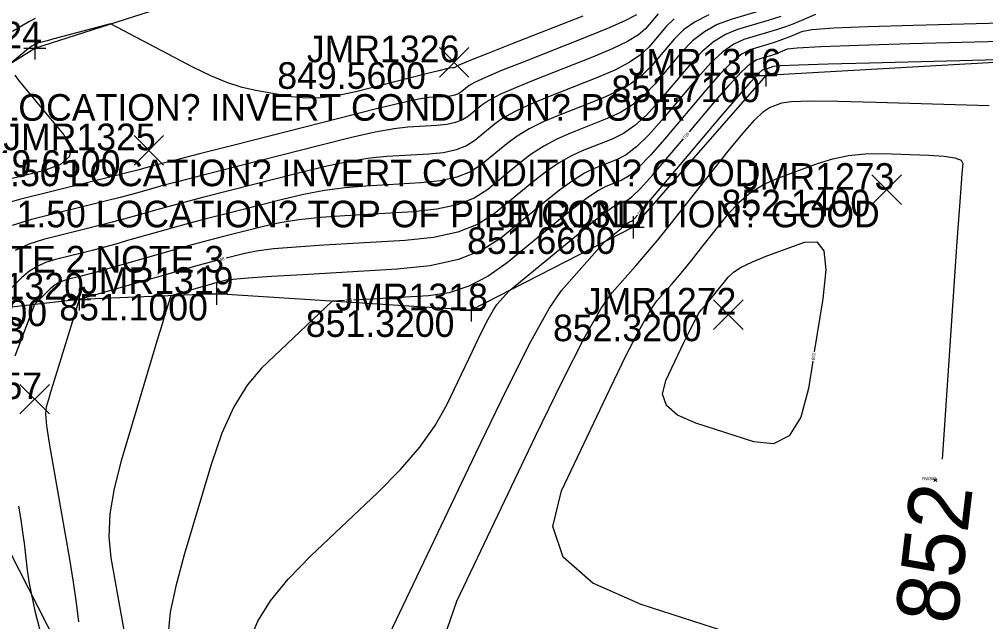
# Model space of a CAD drawing. Extents: x 1654928 to 1810050, y 486881 to 626330.
# Drawn here: x 1801470.61 to 1801514.13, y 489797.37 to 489824.51 of the extents above; entities that cross this region are included whole.
import ezdxf

# ---------------------------------------------------------------- set-up
doc = ezdxf.new("R2010")
doc.units = 0
for name, color, linetype in [('DT_X_Contour_Major', 7, 'Continuous'), ('DT_X_Contour_Minor', 7, 'Continuous'), ('GK_Visualization', 7, 'Continuous'), ('RD_X_Fence', 7, 'Continuous'), ('SV_X_Break_Lines', 7, 'Continuous'), ('SV_X_Random_Point', 7, 'Continuous'), ('SV_X_Shot_Marker', 7, 'Continuous'), ('SV_X_Text_Comment', 7, 'Continuous'), ('SV_X_Text_Elevation', 7, 'Continuous'), ('SV_X_Text_Name', 7, 'Continuous'), ('SV_X_Top_of_Bank', 7, 'Continuous')]:
    doc.layers.add(name, color=color, linetype=linetype)

msp = doc.modelspace()

# ---------------------------------------------------------------- linework, layer by layer
at = {"layer": 'DT_X_Contour_Major'}
for points in [[(1801499.38, 489824.763), (1801498.806, 489824.082), (1801498.496, 489823.811), (1801497.996, 489823.508), (1801497.307, 489823.172), (1801496.427, 489822.805), (1801493.829, 489821.783), (1801492.948, 489821.425), (1801492.255, 489821.116), (1801491.749, 489820.857), (1801491.431, 489820.646), (1801490.831, 489820.152), (1801490.574, 489819.987), (1801490.25, 489819.86), (1801489.862, 489819.773), (1801489.407, 489819.725), (1801488.108, 489819.65), (1801487.495, 489819.578), (1801486.631, 489819.417), (1801485.515, 489819.168), (1801484.147, 489818.83), (1801478.825, 489817.469), (1801477.797, 489817.203), (1801477.078, 489817.014), (1801476.67, 489816.903), (1801475.994, 489816.709), (1801475.656, 489816.616), (1801475.15, 489816.484), (1801474.475, 489816.312), (1801471.158, 489815.484), (1801470.29, 489815.226)], [(1801506.463, 489824.72), (1801505.733, 489824.408), (1801505.441, 489824.29), (1801505.113, 489824.17), (1801504.749, 489824.049), (1801504.348, 489823.925), (1801503.231, 489823.594), (1801502.788, 489823.394), (1801502.296, 489823.043), (1801501.755, 489822.542), (1801501.166, 489821.889), (1801499.53, 489819.947), (1801498.945, 489819.291), (1801498.416, 489818.778), (1801497.944, 489818.41), (1801497.528, 489818.186), (1801496.495, 489817.78), (1801496.064, 489817.57), (1801495.546, 489817.248), (1801494.941, 489816.812), (1801494.249, 489816.262), (1801492.287, 489814.645), (1801491.445, 489814.102), (1801490.387, 489813.689), (1801489.115, 489813.404), (1801487.628, 489813.248), (1801483.376, 489813.002), (1801481.964, 489812.917), (1801480.917, 489812.847), (1801480.234, 489812.79), (1801479.916, 489812.749), (1801479.554, 489812.656), (1801479.4, 489812.616), (1801479.211, 489812.564), (1801478.987, 489812.501), (1801477.431, 489812.055), (1801477.137, 489811.108), (1801477.034, 489810.768), (1801476.848, 489810.152), (1801475.196, 489804.621), (1801474.875, 489803.37), (1801474.691, 489802.225), (1801474.644, 489801.185), (1801474.734, 489800.25), (1801475.156, 489797.899), (1801475.311, 489796.983)], [(1801497.199, 489807.839), (1801497.945, 489809.374), (1801498.547, 489810.55), (1801499.007, 489811.366), (1801499.323, 489811.822), (1801499.974, 489812.559), (1801500.244, 489812.872), (1801500.563, 489813.255), (1801500.933, 489813.71), (1801501.352, 489814.236), (1801502.537, 489815.733), (1801503.01, 489816.256), (1801503.539, 489816.699), (1801504.125, 489817.064), (1801504.767, 489817.351), (1801506.556, 489818.01), (1801507.241, 489818.223), (1801507.956, 489818.369), (1801508.699, 489818.446), (1801509.471, 489818.456), (1801511.568, 489818.391), (1801512.253, 489818.349), (1801512.738, 489818.271), (1801513.022, 489818.158), (1801513.104, 489818.009), (1801513.056, 489817.564), (1801513.02, 489817.111), (1801512.947, 489816.088), (1801512.836, 489814.493), (1801512.247, 489805.791), (1801512.167, 489804.693)], [(1801511.18, 489796.356), (1801511.157, 489796.211), (1801510.687, 489795.44), (1801509.604, 489795.13), (1801507.907, 489795.282), (1801505.597, 489795.895), (1801498.619, 489798.146), (1801496.431, 489799.099), (1801495.102, 489800.27), (1801494.631, 489801.658), (1801495.019, 489803.265), (1801497.199, 489807.839)]]:
    msp.add_lwpolyline(points, dxfattribs=at)
at = {"layer": 'DT_X_Contour_Minor'}
for points in [[(1801501.666, 489824.705), (1801501.043, 489824.395), (1801500.519, 489824.031), (1801500.094, 489823.614), (1801499.096, 489822.428), (1801498.676, 489822.003), (1801498.164, 489821.616), (1801497.562, 489821.267), (1801496.868, 489820.957), (1801494.895, 489820.182), (1801494.195, 489819.883), (1801493.571, 489819.569), (1801493.026, 489819.239), (1801492.558, 489818.893), (1801491.414, 489817.949), (1801490.922, 489817.633), (1801490.305, 489817.392), (1801489.563, 489817.225), (1801488.695, 489817.134), (1801486.215, 489816.991), (1801485.283, 489816.914), (1801484.345, 489816.789), (1801483.402, 489816.617), (1801482.454, 489816.398), (1801479.92, 489815.75), (1801479.02, 489815.517), (1801478.223, 489815.307), (1801477.527, 489815.118), (1801476.933, 489814.952), (1801475.484, 489814.536), (1801474.951, 489814.385), (1801474.437, 489814.244), (1801473.944, 489814.114), (1801473.47, 489813.993), (1801472.233, 489813.685), (1801471.789, 489813.546), (1801471.385, 489813.36), (1801471.02, 489813.127), (1801470.696, 489812.847), (1801469.273, 489811.433)], [(1801498.406, 489824.715), (1801497.912, 489824.454), (1801497.179, 489824.125), (1801496.207, 489823.729), (1801493.296, 489822.584), (1801492.325, 489822.196), (1801491.597, 489821.89), (1801491.111, 489821.666), (1801490.867, 489821.523), (1801490.54, 489821.254), (1801490.399, 489821.163), (1801490.223, 489821.095), (1801490.011, 489821.047), (1801489.763, 489821.021), (1801489.055, 489820.98), (1801488.602, 489820.91), (1801487.774, 489820.731), (1801486.571, 489820.444), (1801484.993, 489820.047), (1801480.286, 489818.843), (1801478.728, 489818.444), (1801477.584, 489818.15), (1801476.854, 489817.962), (1801476.538, 489817.878), (1801476.249, 489817.795), (1801476.009, 489817.731), (1801475.506, 489817.604), (1801474.74, 489817.411), (1801473.712, 489817.155), (1801470.62, 489816.384), (1801469.571, 489816.097)], [(1801495.987, 489824.653), (1801492.762, 489823.385), (1801491.702, 489822.967), (1801490.938, 489822.663), (1801490.472, 489822.474), (1801490.303, 489822.4), (1801490.249, 489822.355), (1801490.225, 489822.34), (1801490.196, 489822.329), (1801490.161, 489822.321), (1801490.119, 489822.317), (1801490.001, 489822.31), (1801489.853, 489822.28), (1801489.497, 489822.194), (1801488.934, 489822.053), (1801488.162, 489821.857), (1801485.829, 489821.26), (1801484.988, 489821.078), (1801484.215, 489820.977), (1801483.51, 489820.958), (1801482.873, 489821.021), (1801481.265, 489821.299), (1801480.637, 489821.443), (1801479.959, 489821.665), (1801479.231, 489821.966), (1801478.454, 489822.345), (1801474.71, 489824.3), (1801472.573, 489823.732), (1801472.166, 489823.624), (1801471.862, 489823.543), (1801471.562, 489823.463), (1801471.436, 489823.429), (1801471.39, 489823.415), (1801471.347, 489823.399), (1801471.307, 489823.38), (1801471.27, 489823.36), (1801471.174, 489823.303), (1801471.126, 489823.27), (1801471.052, 489823.215), (1801470.953, 489823.136), (1801470.829, 489823.035), (1801470.191, 489822.507)], [(1801504.416, 489825.023), (1801502.67, 489824.505), (1801502.04, 489824.268), (1801501.46, 489823.944), (1801500.931, 489823.535), (1801500.452, 489823.039), (1801499.241, 489821.601), (1801498.765, 489821.099), (1801498.248, 489820.67), (1801497.689, 489820.315), (1801497.088, 489820.034), (1801495.429, 489819.381), (1801494.818, 489819.112), (1801494.23, 489818.795), (1801493.664, 489818.43), (1801493.122, 489818.016), (1801491.705, 489816.848), (1801491.096, 489816.456), (1801490.332, 489816.157), (1801489.413, 489815.952), (1801488.34, 489815.839), (1801485.269, 489815.661), (1801484.177, 489815.582), (1801483.202, 489815.475), (1801482.346, 489815.341), (1801481.608, 489815.181), (1801479.798, 489814.718), (1801479.118, 489814.542), (1801478.436, 489814.359), (1801477.751, 489814.171), (1801477.064, 489813.976), (1801475.229, 489813.45), (1801474.598, 489813.27), (1801474.081, 489813.124), (1801473.678, 489813.014), (1801473.389, 489812.939), (1801472.771, 489812.785), (1801472.549, 489812.715), (1801472.347, 489812.622), (1801472.164, 489812.506), (1801472.002, 489812.366), (1801471.291, 489811.659), (1801470.402, 489809.332)], [(1801504.896, 489824.632), (1801504.382, 489824.474), (1801502.95, 489824.05), (1801502.414, 489823.831), (1801501.878, 489823.494), (1801501.343, 489823.038), (1801500.809, 489822.464), (1801499.385, 489820.774), (1801498.855, 489820.195), (1801498.332, 489819.724), (1801497.816, 489819.363), (1801497.308, 489819.11), (1801495.962, 489818.58), (1801495.441, 489818.341), (1801494.888, 489818.021), (1801494.303, 489817.621), (1801493.685, 489817.139), (1801491.996, 489815.746), (1801491.27, 489815.279), (1801490.36, 489814.923), (1801489.264, 489814.678), (1801487.984, 489814.543), (1801484.323, 489814.332), (1801483.07, 489814.249), (1801482.06, 489814.161), (1801481.29, 489814.066), (1801480.762, 489813.965), (1801479.922, 489813.75)], [(1801471.323, 489824.552), (1801471.038, 489824.396), (1801470.306, 489823.96)], [(1801500.106, 489824.528), (1801499.737, 489824.188), (1801498.951, 489823.255), (1801498.586, 489822.907), (1801498.08, 489822.562), (1801497.434, 489822.22), (1801496.647, 489821.881), (1801494.362, 489820.983), (1801493.571, 489820.654), (1801492.913, 489820.342), (1801492.387, 489820.048), (1801491.994, 489819.77), (1801491.122, 489819.051), (1801490.748, 489818.81), (1801490.278, 489818.626), (1801489.712, 489818.499), (1801489.051, 489818.43), (1801487.162, 489818.321), (1801486.389, 489818.246), (1801485.488, 489818.103), (1801484.458, 489817.893), (1801483.301, 489817.614), (1801480.042, 489816.781), (1801478.923, 489816.493), (1801478.01, 489816.255), (1801477.303, 489816.066), (1801476.801, 489815.927), (1801475.739, 489815.622), (1801475.303, 489815.5), (1801474.794, 489815.364), (1801474.209, 489815.213), (1801473.551, 489815.047), (1801471.695, 489814.584), (1801471.029, 489814.376), (1801470.423, 489814.097)], [(1801517.098, 489824.395), (1801510.885, 489824.235), (1801508.823, 489824.172), (1801507.293, 489824.103), (1801506.296, 489824.028), (1801505.833, 489823.947), (1801505.309, 489823.723), (1801505.099, 489823.638), (1801504.864, 489823.552), (1801504.602, 489823.465), (1801504.314, 489823.376), (1801503.512, 489823.138), (1801503.162, 489822.957), (1801502.714, 489822.593), (1801502.168, 489822.045), (1801501.524, 489821.314), (1801499.675, 489819.12), (1801499.035, 489818.387), (1801498.5, 489817.833), (1801498.071, 489817.458), (1801497.748, 489817.262), (1801497.028, 489816.979), (1801496.687, 489816.799), (1801496.205, 489816.474), (1801495.58, 489816.003), (1801494.813, 489815.385), (1801492.579, 489813.543), (1801491.729, 489812.932), (1801490.857, 489812.48), (1801489.962, 489812.188), (1801489.043, 489812.054), (1801485.679, 489811.86)], [(1801500.788, 489819.442), (1801501.881, 489820.739), (1801502.58, 489821.549), (1801503.132, 489822.142), (1801503.536, 489822.52), (1801503.792, 489822.683), (1801504.28, 489822.827), (1801504.455, 489822.881), (1801504.614, 489822.934), (1801504.757, 489822.986), (1801504.885, 489823.038), (1801505.203, 489823.174), (1801505.638, 489823.228), (1801506.702, 489823.285), (1801508.395, 489823.347), (1801510.719, 489823.412), (1801517.754, 489823.593)], [(1801498.72, 489816.002), (1801499.214, 489816.579), (1801499.965, 489817.466), (1801502.238, 489820.164), (1801502.992, 489821.052), (1801503.549, 489821.692), (1801503.91, 489822.083), (1801504.073, 489822.227), (1801504.246, 489822.278), (1801504.308, 489822.297), (1801504.365, 489822.316), (1801504.415, 489822.335), (1801504.461, 489822.353), (1801504.574, 489822.401), (1801504.875, 489822.424), (1801505.695, 489822.456), (1801507.033, 489822.497), (1801508.89, 489822.546), (1801518.763, 489822.8)], [(1801470.411, 489821.994), (1801470.608, 489821.729), (1801470.918, 489821.341), (1801471.341, 489820.829), (1801472.617, 489819.301), (1801472.918, 489818.77), (1801472.865, 489818.323), (1801472.456, 489817.962), (1801471.692, 489817.685), (1801469.182, 489817.059)], [(1801489.437, 489795.771), (1801490.318, 489798.3), (1801493.86, 489805.733), (1801495.072, 489808.228), (1801496.051, 489810.138), (1801496.797, 489811.465), (1801497.311, 489812.206), (1801498.37, 489813.405), (1801498.808, 489813.912), (1801499.327, 489814.535), (1801499.927, 489815.274), (1801500.609, 489816.129), (1801502.534, 489818.562), (1801503.192, 489819.37), (1801503.722, 489819.969), (1801504.123, 489820.36), (1801504.395, 489820.541), (1801504.95, 489820.745), (1801505.371, 489820.805), (1801506.217, 489820.831), (1801507.489, 489820.823), (1801509.186, 489820.781), (1801514.279, 489820.623)], [(1801480.992, 489796.533), (1801481.349, 489797.394), (1801481.926, 489798.313), (1801482.722, 489799.292), (1801483.738, 489800.33), (1801486.737, 489803.175), (1801487.776, 489804.223), (1801488.642, 489805.232), (1801489.335, 489806.201), (1801489.856, 489807.132), (1801491.014, 489809.562), (1801491.409, 489810.376), (1801491.724, 489810.996), (1801491.961, 489811.421), (1801492.119, 489811.653), (1801492.673, 489812.279), (1801495.881, 489814.924), (1801496.502, 489815.428), (1801496.989, 489815.804), (1801497.342, 489816.055), (1801497.562, 489816.178), (1801497.969, 489816.338), (1801498.199, 489816.505), (1801498.584, 489816.887), (1801499.124, 489817.483), (1801499.82, 489818.293), (1801500.517, 489819.121)], [(1801487.107, 489796.463), (1801491.16, 489804.967), (1801492.542, 489807.817), (1801493.647, 489809.986), (1801494.476, 489811.476), (1801495.03, 489812.285), (1801496.967, 489814.477), (1801497.707, 489815.088), (1801497.85, 489815.204), (1801497.963, 489815.291), (1801498.044, 489815.349), (1801498.095, 489815.377), (1801498.189, 489815.414), (1801498.326, 489815.553), (1801498.444, 489815.686)], [(1801500.538, 489809.944), (1801500.818, 489810.52), (1801501.044, 489810.961), (1801501.216, 489811.267), (1801501.334, 489811.438), (1801501.579, 489811.714), (1801501.68, 489811.832), (1801501.799, 489811.975), (1801501.938, 489812.146), (1801502.54, 489812.905), (1801502.768, 489813.119), (1801503.121, 489813.343), (1801503.598, 489813.574), (1801504.199, 489813.815), (1801505.967, 489814.466), (1801506.517, 489814.49), (1801506.839, 489814.073), (1801506.933, 489813.216), (1801506.8, 489811.918), (1801506.411, 489809.522)], [(1801479.515, 489813.645), (1801479.215, 489813.566), (1801478.648, 489813.411), (1801477.975, 489813.223), (1801477.195, 489813.001), (1801473.308, 489811.885), (1801472.117, 489808.046), (1801472.015, 489807.712), (1801471.947, 489807.487), (1801471.811, 489807.034), (1801471.793, 489806.74), (1801471.839, 489806.2), (1801471.95, 489805.413), (1801472.125, 489804.379), (1801472.678, 489801.293), (1801472.871, 489800.179), (1801473.036, 489799.153), (1801473.171, 489798.214), (1801473.277, 489797.362)], [(1801485.26, 489811.836), (1801484.703, 489811.804), (1801481.521, 489808.786), (1801480.868, 489808.029), (1801480.271, 489807.054), (1801479.731, 489805.859), (1801479.248, 489804.445), (1801478.035, 489800.382), (1801477.651, 489798.973), (1801477.408, 489797.793), (1801477.305, 489796.843)], [(1801506.344, 489809.108), (1801506.143, 489807.869), (1801505.805, 489806.58), (1801505.283, 489805.75), (1801504.577, 489805.378), (1801503.687, 489805.465), (1801501.07, 489806.309), (1801500.25, 489806.667), (1801499.752, 489807.106), (1801499.575, 489807.627), (1801499.721, 489808.229), (1801500.538, 489809.944)], [(1801470.575, 489802.579), (1801470.676, 489801.954), (1801470.757, 489801.397), (1801470.819, 489800.907), (1801470.957, 489799.689), (1801471.031, 489799.181), (1801471.149, 489798.572), (1801471.311, 489797.86), (1801471.517, 489797.046)]]:
    msp.add_lwpolyline(points, dxfattribs=at)
at = {"layer": 'GK_Visualization'}
for p, q in [((1801511.801, 489803.678), (1801511.934, 489803.812)), ((1801511.801, 489803.812), (1801511.934, 489803.678))]:
    msp.add_line(p, q, dxfattribs=at)
at = {"layer": 'RD_X_Fence'}
msp.add_lwpolyline([(1801551.601, 489647.601), (1801542.924, 489663.468), (1801525.109, 489695.967), (1801509.688, 489725.543), (1801495.067, 489753.216), (1801479.522, 489782.185), (1801467.623, 489805.516), (1801461.848, 489815.569), (1801444.198, 489848.97), (1801434.479, 489868.8), (1801422.196, 489892.762), (1801414.797, 489907.008)], dxfattribs=at)
at = {"layer": 'SV_X_Break_Lines'}
msp.add_lwpolyline([(1801462.765, 489817.856), (1801471.304, 489823.205), (1801489.468, 489829.043)], dxfattribs=at)
at = {"layer": 'SV_X_Random_Point'}
for p, q in [((1801489.524, 489821.908), (1801490.857, 489823.243)), ((1801489.524, 489823.243), (1801490.857, 489821.908)), ((1801475.773, 489817.942), (1801477.107, 489819.277)), ((1801475.773, 489819.277), (1801477.107, 489817.942)), ((1801509.003, 489816.161), (1801510.336, 489817.496)), ((1801509.003, 489817.496), (1801510.336, 489816.161)), ((1801501.875, 489810.54), (1801503.208, 489811.875)), ((1801501.875, 489811.875), (1801503.208, 489810.54)), ((1801470.637, 489806.728), (1801471.97, 489808.063)), ((1801470.637, 489808.063), (1801471.97, 489806.728))]:
    msp.add_line(p, q, dxfattribs=at)
at = {"layer": 'SV_X_Shot_Marker'}
for p, q in [((1801471.304, 489823.705), (1801471.304, 489822.705)), ((1801470.804, 489823.205), (1801471.804, 489823.205)), ((1801471.304, 489823.205), (1801471.304, 489823.205)), ((1801504.227, 489822.476), (1801504.227, 489821.476)), ((1801503.727, 489821.976), (1801504.727, 489821.976)), ((1801504.227, 489821.976), (1801504.227, 489821.976)), ((1801498.255, 489815.637), (1801498.255, 489814.637)), ((1801497.755, 489815.137), (1801498.755, 489815.137)), ((1801498.255, 489815.137), (1801498.255, 489815.137)), ((1801479.493, 489812.64), (1801479.493, 489811.64)), ((1801473.308, 489812.385), (1801473.308, 489811.385)), ((1801478.993, 489812.14), (1801479.993, 489812.14)), ((1801479.493, 489812.14), (1801479.493, 489812.14)), ((1801472.808, 489811.885), (1801473.808, 489811.885)), ((1801473.308, 489811.885), (1801473.308, 489811.885)), ((1801490.955, 489811.9), (1801490.955, 489810.9)), ((1801490.455, 489811.4), (1801491.455, 489811.4)), ((1801490.955, 489811.4), (1801490.955, 489811.4))]:
    msp.add_line(p, q, dxfattribs=at)
at = {"layer": 'SV_X_Top_of_Bank'}
msp.add_lwpolyline([(1801559.863, 489822.721), (1801539.336, 489827.057), (1801528.648, 489823.028), (1801533.885, 489825.215), (1801524.048, 489823.1), (1801504.227, 489821.976), (1801498.255, 489815.137), (1801490.955, 489811.4), (1801479.493, 489812.14), (1801473.308, 489811.885), (1801466.247, 489811.095)], dxfattribs=at)

# ---------------------------------------------------------------- texts
at = {"layer": 'DT_X_Contour_Major'}
msp.add_text('852', height=2.8, rotation=83.2466, dxfattribs=at).set_placement((1801512.817, 489797.192))
at = {"layer": 'DT_X_Contour_Minor'}
for s, rotation, p in [('851', 229.8864, (1801500.685, 489819.428)), ('852', 228.7897, (1801498.634, 489816.009)), ('851', 194.4937, (1801479.83, 489813.799)), ('851', 183.3041, (1801485.598, 489811.925)), ('852', 80.7776, (1801506.421, 489809.147))]:
    msp.add_text(s, height=0.14, rotation=rotation, dxfattribs=at).set_placement(p)
at = {"layer": 'GK_Visualization'}
msp.add_text('RW303', height=0.14, dxfattribs=at).set_placement((1801511.264, 489803.745))
at = {"layer": 'SV_X_Text_Comment'}
for s, p in [('EL*RCP SIZE? 4.50 LOCATION? INVERT CONDITION? POOR', (1801454.778, 489819.938)), ('EL*CPP SIZE? 1.50 LOCATION? INVERT CONDITION? GOOD', (1801458.064, 489816.99)), ('BL*CPP SIZE? 1.50 LOCATION? TOP OF PIPE CONDITION? GOOD', (1801459.243, 489815.136)), ('NOTE 1 DELINEATOR NOTE 2 NOTE 3', (1801450.85, 489813.101)), ('EL*TB', (1801466.247, 489809.894))]:
    msp.add_text(s, height=1.2, dxfattribs=at).set_placement(p)
at = {"layer": 'SV_X_Text_Elevation'}
for s, p in [('849.5600', (1801482.226, 489821.376)), ('851.7100', (1801497.275, 489820.776)), ('849.6500', (1801468.475, 489817.41)), ('852.1400', (1801502.234, 489815.628)), ('851.6600', (1801490.773, 489813.937)), ('851.1000', (1801472.408, 489810.94)), ('850.8000', (1801465.164, 489810.685)), ('851.3200', (1801483.511, 489810.2)), ('852.3200', (1801494.643, 489810.007))]:
    msp.add_text(s, height=1.2, dxfattribs=at).set_placement(p)
at = {"layer": 'SV_X_Text_Name'}
for s, p in [('JMR1324', (1801464.757, 489823.205)), ('JMR1326', (1801483.558, 489822.576)), ('JMR1316', (1801498.049, 489821.976)), ('JMR1325', (1801469.883, 489818.61)), ('JMR1273', (1801503.151, 489816.828)), ('JMR1317', (1801492.153, 489815.137)), ('JMR1319', (1801473.381, 489812.14)), ('JMR1320', (1801466.648, 489811.885)), ('JMR1318', (1801484.843, 489811.4)), ('JMR1272', (1801496.032, 489811.207)), ('JMR1257', (1801464.766, 489807.395))]:
    msp.add_text(s, height=1.2, dxfattribs=at).set_placement(p)

doc.saveas('drawing.dxf')
